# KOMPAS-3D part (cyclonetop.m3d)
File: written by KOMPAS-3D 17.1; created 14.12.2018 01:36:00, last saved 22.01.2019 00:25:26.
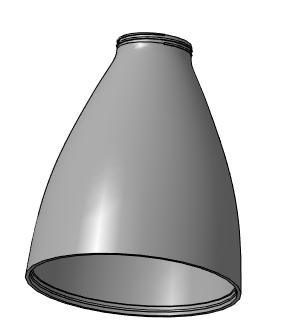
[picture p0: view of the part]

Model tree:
1. Эскиз:1
2. Операция вращения:5
     Угол 1 = 360
3. Смещенная плоскость:1
4. Эскиз:2
5. Спираль цилиндрическая:1
     Число витков = 2; Шаг = 2.5; Высота = 5; Расстояние до объекта = 5; Диаметр 1 = 40.3; Диаметр 2 = 10
6. Эскиз:3
7. Кинематическая операция:1
8. Эскиз:4
9. Вырезать элемент выдавливания:1
     Расстояние 2 = 10
10. Path Part 21 9
     Координата X = 0.041462; Координата Z = -58.8267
